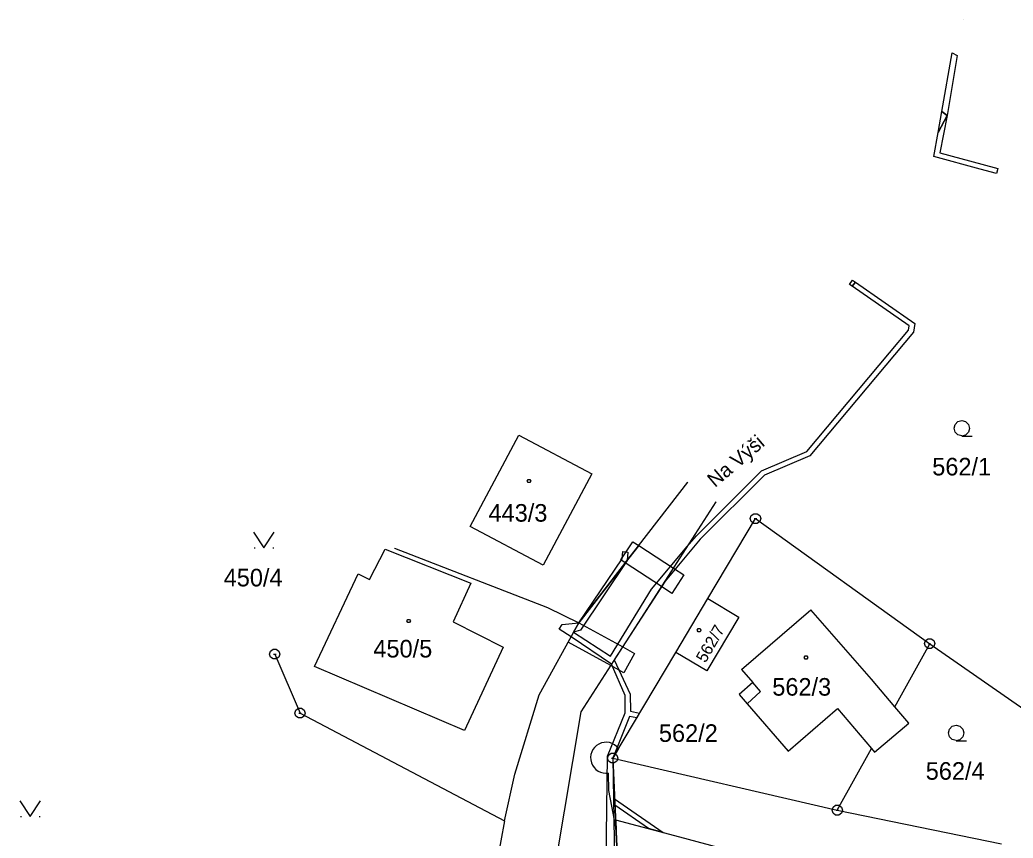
# Model space of a CAD drawing. Extents: x -759699 to -757730, y -1172308 to -1170857.
# Drawn here: x -759267.2 to -759171.2, y -1171575.4 to -1171496.3 of the extents above; entities that cross this region are included whole.
import ezdxf

# ---------------------------------------------------------------- set-up
doc = ezdxf.new("R2010")
doc.units = 0
for name, color, linetype in [('Vrstva 1', 7, 'Continuous'), ('Vrstva 12', 7, 'Continuous'), ('Vrstva 13', 7, 'Continuous'), ('Vrstva 2', 7, 'Continuous'), ('Vrstva 3', 7, 'Continuous'), ('Vrstva 4', 7, 'Continuous'), ('Vrstva 5', 7, 'Continuous'), ('Vrstva 7', 7, 'Continuous'), ('Vrstva 8', 7, 'Continuous')]:
    doc.layers.add(name, color=color, linetype=linetype)

msp = doc.modelspace()

# ---------------------------------------------------------------- linework, layer by layer
at = {"layer": 'Vrstva 1'}
for p, q in [((-759223.67, -1171545.24), (-759218.97, -1171536.42)), ((-759218.97, -1171536.42), (-759211.9, -1171540.16)), ((-759211.9, -1171540.16), (-759216.6, -1171548.99)), ((-759213.17, -1171554.55), (-759202.64, -1171540.96)), ((-759202.64, -1171540.96), (-759202.64, -1171540.96)), ((-759202.64, -1171540.96), (-759202.64, -1171540.96)), ((-759212.95, -1171563.14), (-759199.9, -1171542.85)), ((-759199.9, -1171542.85), (-759199.9, -1171542.85)), ((-759200.7, -1171552.21), (-759196.09, -1171544.48)), ((-759196.09, -1171544.48), (-759179.26, -1171556.57)), ((-759216.6, -1171548.99), (-759223.67, -1171545.24)), ((-759233.38, -1171550.37), (-759231.87, -1171547.44)), ((-759231.87, -1171547.44), (-759223.61, -1171550.71)), ((-759230.97, -1171547.33), (-759230.97, -1171547.33)), ((-759230.97, -1171547.33), (-759216.2, -1171553.06)), ((-759238.69, -1171558.78), (-759234.48, -1171549.81)), ((-759234.48, -1171549.81), (-759233.38, -1171550.37)), ((-759223.61, -1171550.71), (-759225.32, -1171554.44)), ((-759203.8, -1171557.41), (-759200.7, -1171552.21)), ((-759200.7, -1171552.21), (-759197.69, -1171554)), ((-759216.2, -1171553.06), (-759213.17, -1171554.55)), ((-759197.45, -1171559.07), (-759190.76, -1171553.28)), ((-759184.89, -1171560), (-759190.76, -1171553.28)), ((-759225.32, -1171554.44), (-759220.46, -1171556.89)), ((-759216.99, -1171561.52), (-759213.17, -1171554.55)), ((-759197.69, -1171554), (-759200.79, -1171559.2)), ((-759182.64, -1171562.66), (-759179.26, -1171556.57)), ((-759179.26, -1171556.57), (-759166.9, -1171565.2)), ((-759242.54, -1171557.58), (-759242.54, -1171557.58)), ((-759242.54, -1171557.58), (-759240.1, -1171563.28)), ((-759220.46, -1171556.89), (-759224.2, -1171564.95)), ((-759209.89, -1171567.64), (-759203.8, -1171557.41)), ((-759200.79, -1171559.2), (-759203.8, -1171557.41)), ((-759224.2, -1171564.95), (-759238.69, -1171558.78)), ((-759197.45, -1171559.07), (-759196.36, -1171560.32)), ((-759196.36, -1171560.32), (-759197.68, -1171561.47)), ((-759182.64, -1171562.66), (-759184.89, -1171560)), ((-759219.34, -1171569.17), (-759216.99, -1171561.52)), ((-759197.68, -1171561.47), (-759196.91, -1171562.37)), ((-759196.91, -1171562.37), (-759192.93, -1171566.95)), ((-759240.1, -1171563.28), (-759220.33, -1171573.68)), ((-759215.76, -1171580.02), (-759212.95, -1171563.14)), ((-759192.93, -1171566.95), (-759188.18, -1171562.84)), ((-759188.18, -1171562.84), (-759184.88, -1171566.71)), ((-759181.29, -1171564.24), (-759182.64, -1171562.66)), ((-759184.59, -1171567.05), (-759181.29, -1171564.24)), ((-759188.19, -1171572.67), (-759184.88, -1171566.71)), ((-759184.88, -1171566.71), (-759184.59, -1171567.05)), ((-759209.89, -1171567.64), (-759188.19, -1171572.67)), ((-759209.89, -1171567.64), (-759209.07, -1171585.28)), ((-759220.33, -1171573.68), (-759219.34, -1171569.17)), ((-759188.19, -1171572.67), (-759172.32, -1171575.91)), ((-759220.33, -1171573.68), (-759221.15, -1171578))]:
    msp.add_line(p, q, dxfattribs=at)
at = {"layer": 'Vrstva 12'}
for p, q in [((-759223.67, -1171545.24), (-759218.97, -1171536.42)), ((-759218.97, -1171536.42), (-759211.9, -1171540.16)), ((-759211.9, -1171540.16), (-759216.6, -1171548.99)), ((-759216.6, -1171548.99), (-759223.67, -1171545.24)), ((-759233.38, -1171550.37), (-759231.87, -1171547.44)), ((-759231.87, -1171547.44), (-759223.61, -1171550.71)), ((-759238.69, -1171558.78), (-759234.48, -1171549.81)), ((-759234.48, -1171549.81), (-759233.38, -1171550.37)), ((-759223.61, -1171550.71), (-759225.32, -1171554.44)), ((-759203.8, -1171557.41), (-759200.7, -1171552.21)), ((-759200.7, -1171552.21), (-759197.69, -1171554)), ((-759197.45, -1171559.07), (-759190.76, -1171553.28)), ((-759184.89, -1171560), (-759190.76, -1171553.28)), ((-759225.32, -1171554.44), (-759220.46, -1171556.89)), ((-759197.69, -1171554), (-759200.79, -1171559.2)), ((-759220.46, -1171556.89), (-759224.2, -1171564.95)), ((-759200.79, -1171559.2), (-759203.8, -1171557.41)), ((-759224.2, -1171564.95), (-759238.69, -1171558.78)), ((-759197.45, -1171559.07), (-759196.36, -1171560.32)), ((-759195.61, -1171561.19), (-759196.36, -1171560.32)), ((-759182.64, -1171562.66), (-759184.89, -1171560)), ((-759196.91, -1171562.37), (-759195.61, -1171561.19)), ((-759196.91, -1171562.37), (-759192.93, -1171566.95)), ((-759192.93, -1171566.95), (-759188.18, -1171562.84)), ((-759188.18, -1171562.84), (-759184.88, -1171566.71)), ((-759181.29, -1171564.24), (-759182.64, -1171562.66)), ((-759184.59, -1171567.05), (-759181.29, -1171564.24)), ((-759184.88, -1171566.71), (-759184.59, -1171567.05))]:
    msp.add_line(p, q, dxfattribs=at)
at = {"layer": 'Vrstva 13'}
for p, q in [((-759176.04, -1171496.26), (-759176.04, -1171496.26)), ((-759176.04, -1171496.26), (-759176.04, -1171496.26)), ((-759178.09, -1171505.11), (-759177.1, -1171499.45)), ((-759176.6, -1171499.71), (-759177.56, -1171505.49)), ((-759177.1, -1171499.45), (-759176.6, -1171499.71)), ((-759178.45, -1171507.15), (-759178.09, -1171505.11)), ((-759177.56, -1171505.49), (-759178.45, -1171507.15)), ((-759178.45, -1171507.15), (-759177.56, -1171505.49)), ((-759177.56, -1171505.49), (-759178.28, -1171509.1)), ((-759178.09, -1171505.11), (-759177.56, -1171505.49)), ((-759177.56, -1171505.49), (-759178.09, -1171505.11)), ((-759178.86, -1171509.46), (-759178.45, -1171507.15)), ((-759174.39, -1171510.69), (-759178.86, -1171509.46)), ((-759178.28, -1171509.1), (-759174.22, -1171510.22)), ((-759174.22, -1171510.22), (-759172.67, -1171510.64)), ((-759172.8, -1171511.12), (-759174.39, -1171510.69)), ((-759172.67, -1171510.64), (-759172.8, -1171511.12)), ((-759187.01, -1171521.83), (-759186.73, -1171521.42)), ((-759186.74, -1171522.02), (-759187.01, -1171521.83)), ((-759186.42, -1171521.63), (-759186.74, -1171522.02)), ((-759186.74, -1171522.02), (-759186.42, -1171521.63)), ((-759181.25, -1171525.84), (-759186.74, -1171522.02)), ((-759186.73, -1171521.42), (-759186.42, -1171521.63)), ((-759186.42, -1171521.63), (-759180.71, -1171525.6)), ((-759181.3, -1171526.25), (-759181.25, -1171525.84)), ((-759180.71, -1171525.6), (-759180.82, -1171526.46)), ((-759180.82, -1171526.46), (-759190.84, -1171538.42)), ((-759183.15, -1171528.46), (-759181.3, -1171526.25)), ((-759191.14, -1171538), (-759183.15, -1171528.46)), ((-759195.5, -1171539.87), (-759191.14, -1171538)), ((-759190.84, -1171538.42), (-759195.22, -1171540.29)), ((-759201.8, -1171546.13), (-759195.5, -1171539.87)), ((-759195.22, -1171540.29), (-759201.44, -1171546.47)), ((-759209.11, -1171548.47), (-759207.93, -1171546.72)), ((-759207.93, -1171546.72), (-759207.38, -1171547.08)), ((-759201.44, -1171546.47), (-759204.83, -1171550.52)), ((-759202.69, -1171547.18), (-759201.8, -1171546.13)), ((-759208.99, -1171548.35), (-759208.92, -1171547.66)), ((-759208.92, -1171547.66), (-759208.42, -1171547.71)), ((-759207.38, -1171547.08), (-759208.68, -1171548.76)), ((-759208.68, -1171548.76), (-759207.38, -1171547.08)), ((-759208.42, -1171547.71), (-759208.5, -1171548.53)), ((-759207.38, -1171547.08), (-759204.03, -1171549.27)), ((-759206.14, -1171551.3), (-759202.69, -1171547.18)), ((-759213.17, -1171554.55), (-759208.99, -1171548.35)), ((-759208.5, -1171548.53), (-759213.17, -1171554.55)), ((-759213.17, -1171554.55), (-759208.5, -1171548.53)), ((-759208.5, -1171548.53), (-759213.01, -1171555.26)), ((-759208.68, -1171548.76), (-759209.11, -1171548.47)), ((-759205.18, -1171551.05), (-759208.68, -1171548.76)), ((-759203.03, -1171549.92), (-759204.19, -1171551.7)), ((-759204.03, -1171549.27), (-759203.03, -1171549.92)), ((-759204.83, -1171550.52), (-759209.74, -1171558.14)), ((-759210.11, -1171557.77), (-759206.14, -1171551.3)), ((-759204.19, -1171551.7), (-759205.18, -1171551.05)), ((-759215.05, -1171555.17), (-759214.76, -1171554.72)), ((-759214.76, -1171554.72), (-759213.17, -1171554.55)), ((-759214.19, -1171556.42), (-759213.17, -1171554.55)), ((-759213.17, -1171554.55), (-759213.67, -1171555.46)), ((-759213.67, -1171555.46), (-759213.17, -1171554.55)), ((-759213.17, -1171554.55), (-759208.92, -1171556.88)), ((-759213.91, -1171555.9), (-759215.05, -1171555.17)), ((-759213.67, -1171555.46), (-759213.91, -1171555.9)), ((-759213.91, -1171555.9), (-759213.67, -1171555.46)), ((-759213.01, -1171555.26), (-759213.67, -1171555.46)), ((-759213.67, -1171555.46), (-759210.11, -1171557.77)), ((-759210.08, -1171558.67), (-759214.19, -1171556.42)), ((-759209.99, -1171558.54), (-759213.91, -1171555.9)), ((-759208.92, -1171556.88), (-759207.78, -1171557.5)), ((-759207.78, -1171557.5), (-759208.8, -1171559.37)), ((-759208.69, -1171561.57), (-759209.99, -1171558.54)), ((-759209.74, -1171558.14), (-759208.19, -1171561.45)), ((-759208.8, -1171559.37), (-759210.08, -1171558.67)), ((-759208.19, -1171561.45), (-759208.17, -1171563.1)), ((-759208.67, -1171563.26), (-759208.69, -1171561.57)), ((-759210.39, -1171567.45), (-759208.67, -1171563.26)), ((-759208.17, -1171563.1), (-759207.29, -1171563.28)), ((-759207.29, -1171563.28), (-759207.56, -1171563.73)), ((-759208.26, -1171563.59), (-759209.89, -1171567.64)), ((-759207.56, -1171563.73), (-759208.26, -1171563.59)), ((-759209.33, -1171566.69), (-759209.89, -1171567.64)), ((-759210.55, -1171578.67), (-759210.39, -1171567.45)), ((-759209.89, -1171567.64), (-759209.65, -1171582.23)), ((-759209.89, -1171567.64), (-759209.83, -1171568.89)), ((-759210.27, -1171570.75), (-759210.28, -1171569.07)), ((-759209.83, -1171568.89), (-759209.74, -1171570.87)), ((-759209.57, -1171574.47), (-759210.27, -1171570.75)), ((-759209.74, -1171570.87), (-759209.57, -1171574.47)), ((-759209.71, -1171571.55), (-759205.02, -1171574.81)), ((-759209.68, -1171572.18), (-759209.71, -1171571.55)), ((-759206.44, -1171574.43), (-759209.68, -1171572.18)), ((-759209.61, -1171573.58), (-759203.93, -1171575.1)), ((-759209.47, -1171576.76), (-759209.61, -1171573.58)), ((-759205.02, -1171574.81), (-759206.44, -1171574.43)), ((-759203.93, -1171575.1), (-759173.77, -1171583.16))]:
    msp.add_line(p, q, dxfattribs=at)
msp.add_arc((-759210.526, -1171567.592), 1.498, 37.02254, 279.45768, dxfattribs=at)
at = {"layer": 'Vrstva 3'}
for p, q in [((-759244.54, -1171547.29), (-759244.44, -1171547.29)), ((-759242.74, -1171547.29), (-759242.64, -1171547.29)), ((-759267.12, -1171573.27), (-759267.02, -1171573.27)), ((-759265.32, -1171573.27), (-759265.22, -1171573.27))]:
    msp.add_line(p, q, dxfattribs=at)
for points in [[(-759176.15, -1171536.48), (-759176.53, -1171536.38), (-759176.8, -1171536.11), (-759176.9, -1171535.74), (-759176.8, -1171535.37), (-759176.53, -1171535.1), (-759176.16, -1171535), (-759175.79, -1171535.1), (-759175.52, -1171535.37), (-759175.42, -1171535.75), (-759175.52, -1171536.13), (-759175.79, -1171536.4), (-759176.17, -1171536.5), (-759175.17, -1171536.5)], [(-759244.59, -1171545.79), (-759243.59, -1171547.29), (-759242.59, -1171545.79)], [(-759176.7, -1171565.93), (-759177.08, -1171565.83), (-759177.35, -1171565.56), (-759177.45, -1171565.19), (-759177.35, -1171564.82), (-759177.08, -1171564.55), (-759176.71, -1171564.45), (-759176.34, -1171564.55), (-759176.07, -1171564.82), (-759175.97, -1171565.2), (-759176.07, -1171565.58), (-759176.34, -1171565.85), (-759176.72, -1171565.95), (-759175.72, -1171565.95)], [(-759267.17, -1171571.77), (-759266.17, -1171573.27), (-759265.17, -1171571.77)]]:
    msp.add_lwpolyline(points, dxfattribs=at)
at = {"layer": 'Vrstva 4'}
for p, q in [((-759195.61, -1171561.19), (-759196.36, -1171560.32)), ((-759196.91, -1171562.37), (-759195.61, -1171561.19))]:
    msp.add_line(p, q, dxfattribs=at)
at = {"layer": 'Vrstva 5'}
for points in [[(-759217.89, -1171540.69), (-759217.8, -1171540.84), (-759217.89, -1171540.99), (-759218.07, -1171540.99), (-759218.16, -1171540.84), (-759218.07, -1171540.69)], [(-759229.52, -1171554.22), (-759229.43, -1171554.37), (-759229.52, -1171554.52), (-759229.7, -1171554.52), (-759229.79, -1171554.37), (-759229.7, -1171554.22)], [(-759201.45, -1171555.11), (-759201.36, -1171555.26), (-759201.45, -1171555.41), (-759201.63, -1171555.41), (-759201.72, -1171555.26), (-759201.63, -1171555.11)], [(-759191.13, -1171557.75), (-759191.04, -1171557.9), (-759191.13, -1171558.05), (-759191.31, -1171558.05), (-759191.4, -1171557.9), (-759191.31, -1171557.75)]]:
    msp.add_lwpolyline(points, close=True, dxfattribs=at)
at = {"layer": 'Vrstva 8'}
for p, q in [((-759196.21, -1171544.48), (-759195.97, -1171544.48)), ((-759179.38, -1171556.57), (-759179.14, -1171556.57)), ((-759242.66, -1171557.58), (-759242.42, -1171557.58)), ((-759240.22, -1171563.28), (-759239.98, -1171563.28)), ((-759210.01, -1171567.64), (-759209.77, -1171567.64)), ((-759188.31, -1171572.67), (-759188.07, -1171572.67))]:
    msp.add_line(p, q, dxfattribs=at)
for points in [[(-759195.94, -1171544), (-759195.69, -1171544.18), (-759195.59, -1171544.47), (-759195.69, -1171544.76), (-759195.94, -1171544.94), (-759196.25, -1171544.94), (-759196.5, -1171544.76), (-759196.6, -1171544.47), (-759196.5, -1171544.18), (-759196.25, -1171544)], [(-759179.11, -1171556.09), (-759178.86, -1171556.27), (-759178.76, -1171556.56), (-759178.86, -1171556.85), (-759179.11, -1171557.03), (-759179.42, -1171557.03), (-759179.67, -1171556.85), (-759179.77, -1171556.56), (-759179.67, -1171556.27), (-759179.42, -1171556.09)], [(-759242.39, -1171557.1), (-759242.14, -1171557.28), (-759242.04, -1171557.57), (-759242.14, -1171557.86), (-759242.39, -1171558.04), (-759242.7, -1171558.04), (-759242.95, -1171557.86), (-759243.05, -1171557.57), (-759242.95, -1171557.28), (-759242.7, -1171557.1)], [(-759239.95, -1171562.8), (-759239.7, -1171562.98), (-759239.6, -1171563.27), (-759239.7, -1171563.56), (-759239.95, -1171563.74), (-759240.26, -1171563.74), (-759240.51, -1171563.56), (-759240.61, -1171563.27), (-759240.51, -1171562.98), (-759240.26, -1171562.8)], [(-759209.74, -1171567.16), (-759209.49, -1171567.34), (-759209.39, -1171567.63), (-759209.49, -1171567.92), (-759209.74, -1171568.1), (-759210.05, -1171568.1), (-759210.3, -1171567.92), (-759210.4, -1171567.63), (-759210.3, -1171567.34), (-759210.05, -1171567.16)], [(-759188.04, -1171572.19), (-759187.79, -1171572.37), (-759187.69, -1171572.66), (-759187.79, -1171572.95), (-759188.04, -1171573.13), (-759188.35, -1171573.13), (-759188.6, -1171572.95), (-759188.7, -1171572.66), (-759188.6, -1171572.37), (-759188.35, -1171572.19)]]:
    msp.add_lwpolyline(points, close=True, dxfattribs=at)

# ---------------------------------------------------------------- texts
at = {"layer": 'Vrstva 2'}
for s, p in [('562/1', (-759179.016, -1171540.3)), ('443/3', (-759221.887, -1171544.77)), ('450/4', (-759247.477, -1171551.03)), ('450/5', (-759233.014, -1171557.9)), ('562/3', (-759194.471, -1171561.59)), ('562/2', (-759205.427, -1171566.06)), ('562/4', (-759179.644, -1171569.72))]:
    msp.add_text(s, height=1.7, dxfattribs=at).set_placement(p)
msp.add_text('562/7', height=1.14, rotation=60.04598, dxfattribs=at).set_placement((-759200.926, -1171558.491))
at = {"layer": 'Vrstva 7'}
msp.add_text('Na Výši', height=1.4, rotation=40.33623, dxfattribs=at).set_placement((-759200.008, -1171541.519))

doc.saveas('drawing.dxf')
